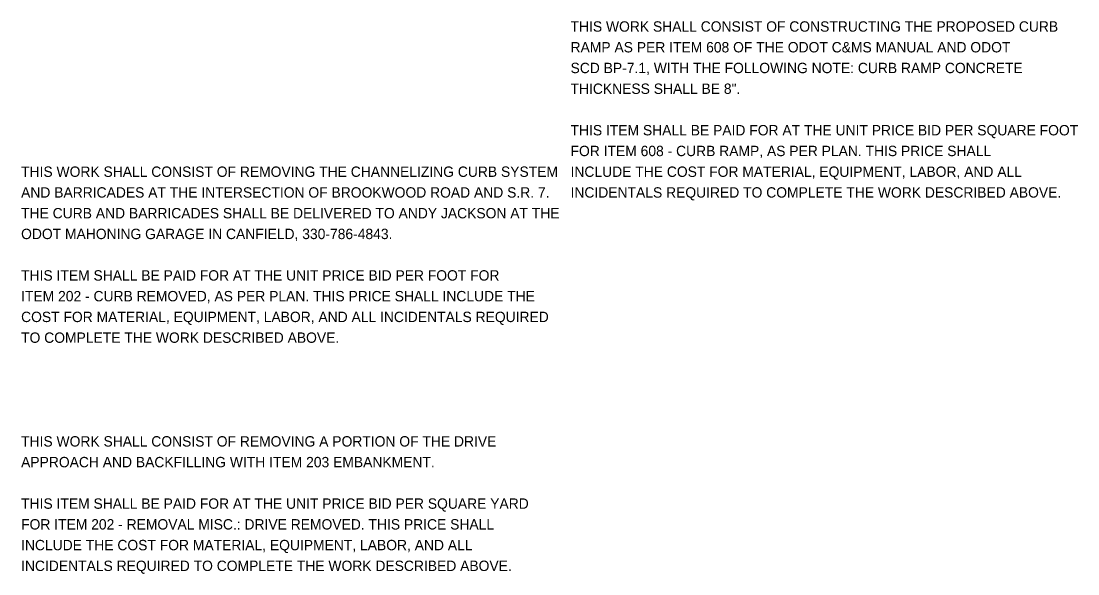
# Model space of a CAD drawing. Extents: x 0 to 52.6, y 0 to 28.5.
# Drawn here: x 38.3 to 52.57, y 1.8 to 9.26 of the extents above; entities that cross this region are included whole.
import ezdxf

# ---------------------------------------------------------------- set-up
doc = ezdxf.new("R2010")
doc.units = 0
doc.layers.add('SH_Text', color=7, linetype='Continuous')

msp = doc.modelspace()

# ---------------------------------------------------------------- texts
at = {"layer": 'SH_Text'}
for s, p in [('THIS WORK SHALL CONSIST OF CONSTRUCTING THE PROPOSED CURB', (45.715, 9.12)), ('RAMP AS PER ITEM 608 OF THE ODOT C&MS MANUAL AND ODOT', (45.715, 8.84)), ('SCD BP-7.1, WITH THE FOLLOWING NOTE: CURB RAMP CONCRETE', (45.715, 8.56)), ('THICKNESS SHALL BE 8".', (45.715, 8.28)), ('THIS ITEM SHALL BE PAID FOR AT THE UNIT PRICE BID PER SQUARE FOOT', (45.715, 7.72)), ('FOR ITEM 608 - CURB RAMP, AS PER PLAN. THIS PRICE SHALL', (45.715, 7.44)), ('THIS WORK SHALL CONSIST OF REMOVING THE CHANNELIZING CURB SYSTEM ', (38.295, 7.16)), ('INCLUDE THE COST FOR MATERIAL, EQUIPMENT, LABOR, AND ALL ', (45.715, 7.16)), ('AND BARRICADES AT THE INTERSECTION OF BROOKWOOD ROAD AND S.R. 7. ', (38.295, 6.88)), ('INCIDENTALS REQUIRED TO COMPLETE THE WORK DESCRIBED ABOVE.', (45.715, 6.88)), ('THE CURB AND BARRICADES SHALL BE DELIVERED TO ANDY JACKSON AT THE ', (38.295, 6.6)), ('ODOT MAHONING GARAGE IN CANFIELD, 330-786-4843.', (38.295, 6.32)), ('THIS ITEM SHALL BE PAID FOR AT THE UNIT PRICE BID PER FOOT FOR ', (38.295, 5.76)), ('ITEM 202 - CURB REMOVED, AS PER PLAN. THIS PRICE SHALL INCLUDE THE ', (38.295, 5.48)), ('COST FOR MATERIAL, EQUIPMENT, LABOR, AND ALL INCIDENTALS REQUIRED ', (38.295, 5.2)), ('TO COMPLETE THE WORK DESCRIBED ABOVE.', (38.295, 4.92)), ('THIS WORK SHALL CONSIST OF REMOVING A PORTION OF THE DRIVE ', (38.295, 3.52)), ('APPROACH AND BACKFILLING WITH ITEM 203 EMBANKMENT.', (38.295, 3.24)), ('THIS ITEM SHALL BE PAID FOR AT THE UNIT PRICE BID PER SQUARE YARD', (38.295, 2.68)), ('FOR ITEM 202 - REMOVAL MISC.: DRIVE REMOVED. THIS PRICE SHALL', (38.295, 2.4)), ('INCLUDE THE COST FOR MATERIAL, EQUIPMENT, LABOR, AND ALL ', (38.295, 2.12)), ('INCIDENTALS REQUIRED TO COMPLETE THE WORK DESCRIBED ABOVE.', (38.295, 1.84))]:
    msp.add_text(s, height=0.14, dxfattribs=at).set_placement(p)

doc.saveas('drawing.dxf')
